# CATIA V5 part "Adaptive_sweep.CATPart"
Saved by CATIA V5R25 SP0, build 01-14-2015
Part number: Part1
Bounding box of the stored display mesh (mm): x -106.531 to 0, y -4.546 to 2.643, z -53.351 to 74.079
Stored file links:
  E:\cadcim\GSD_cat_v5-6r2014\Part_files\Adaptive_sweep.CATPart
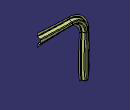
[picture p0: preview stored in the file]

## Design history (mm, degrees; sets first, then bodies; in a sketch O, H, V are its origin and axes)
Body1 (main body)
  Sketch1 on zx-plane, origin (0, 0, 0), H (-1, 0, 0), V (0, 0, 1)
    point P1 (0, 61.5796)
    line L1 (0, 61.5796) -> (65, 61.5796)
    line L2 (94.9999, 31.6495) -> (94.9999, -53.3505)
    point P2 (94.9999, -53.3505)
    arc A1 centre (64.9999, 31.5796) radius 30 from (65, 61.5796) to (94.9999, 31.6495) cw
    radius A1 = 30
    length L1 = 65
    length L2 = 85
    coincidence: P1 V
    horizontal: L1 H
    vertical: L2 V
    tangency: A1 L1, A1 L2
  Sketch2 on {plane type Normal, Curve Sketch1, RefPoint Sketch1.P2}, origin (-94.9999, 0, -53.3505), H (1, 0, 0), V (0, 1, 0)
    point P1 (-5.022, -3.8355)
    line L1 (-4.7817, -3.2105) -> (-2.9, 1.6817)
    point P2 (-2.522, 2.6645)
    line L2 (-5.8642, -3.8355) -> (-8.8642, -3.8355)
    point P3 (-8.8642, -3.8355)
    arc A1 centre (-1.5, 1.1433) radius 1.5 from (-2.9, 1.6817) to (-1.5, 2.6433) cw
    point P4 (-2.9, 1.6817)
    point P5 (-1.5, 2.6433)
    line L3 (-5.8642, -3.8355) -> (-4.7817, -3.2105)
    point P7 (-5.8642, -3.8355)
    point P8 (-4.7817, -3.2105)
    point P9 (5.022, -3.8355)
    point P10 (2.522, 2.6645)
    point P11 (8.8642, -3.8355)
    point P12 (2.9, 1.6817)
    point P13 (1.5, 2.6433)
    point P15 (5.8642, -3.8355)
    point P16 (4.7817, -3.2105)
    line L4 (4.7817, -3.2105) -> (2.9, 1.6817)
    line L5 (5.8642, -3.8355) -> (8.8642, -3.8355)
    arc A2 centre (1.5, 1.1433) radius 1.5 from (2.9, 1.6817) to (1.5, 2.6433) ccw
    line L6 (5.8642, -3.8355) -> (4.7817, -3.2105)
    line L7 (-1.5, 2.6433) -> (1.5, 2.6433)
    distance P2 P1 V = 6.5
    radius A1 = 1.5
    angle L2 L3 = 30
    length L3 = 1.25
    length L2 = 3
    length L7 = 3
    horizontal: L2 H
    coincidence: L1 P2, L2 P1, L1 P1
    tangency: A1 L1, L7 A1
    symmetry: P1 P9 V, P2 P10 V, P3 P11 V, P4 P12 V, P5 P13 V, P7 P15 V, P8 P16 V, L1 L4 V, L2 L5 V, A1 A2 V, L3 L6 V
  SweepSketch1: Spine Sketch1, Sketch Sketch2, ListSketches (a sketch; a sketch; a sketch; a sketch), SectionVertices ({point type OnCurve, Support Sketch1, Ratio 0}; Sketch1.P1; {point type OnCurve, Support Sketch1, Ratio 0.154867}; {point type OnCurve, Support Sketch1, Ratio 0.572067})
